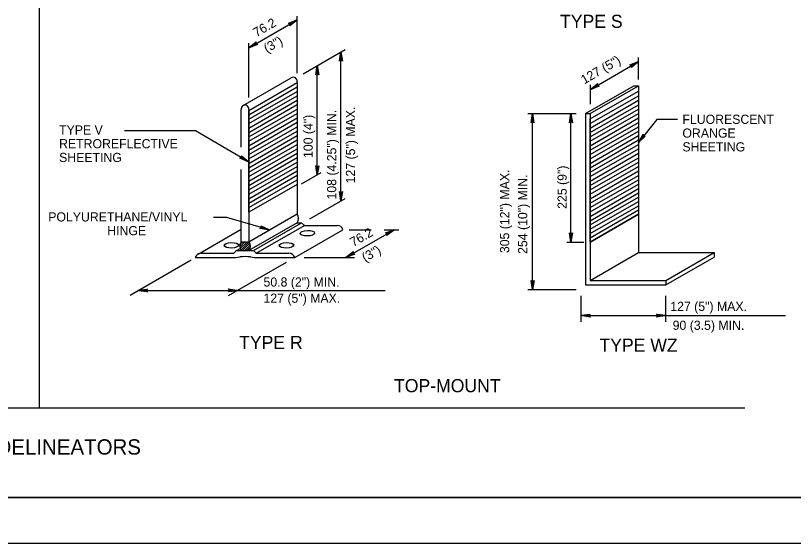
# Model space of a CAD drawing. Extents: x 640253 to 641999, y 298458 to 299646.
# Drawn here: x 640544.6 to 640798.8, y 298457.6 to 298630.1 of the extents above; entities that cross this region are included whole.
import ezdxf

# ---------------------------------------------------------------- set-up
doc = ezdxf.new("R2010")
doc.units = 0
for name, color, linetype in [('1', 7, 'Continuous'), ('2', 7, 'Continuous'), ('PLT-BNDY', 7, 'Continuous')]:
    doc.layers.add(name, color=color, linetype=linetype)

msp = doc.modelspace()

# ---------------------------------------------------------------- linework, layer by layer
at = {"layer": '1'}
for p, q in [((640552.4, 298501.97), (640552.4, 298787.67)), ((640318.26, 298501.97), (640782.88, 298501.97)), ((641079.31, 298472.63), (640293.31, 298472.63)), ((640293.31, 298472.63), (640879.31, 298472.63))]:
    msp.add_line(p, q, dxfattribs=at)
at = {"layer": '2'}
for p, q in [((640620.86, 298619.6), (640636.6, 298628.69)), ((640636.6, 298611.27), (640636.6, 298629.99)), ((640620.86, 298603.34), (640620.86, 298621.06)), ((640638.58, 298611.11), (640652.31, 298619.04)), ((640650.95, 298569.6), (640650.95, 298618.26)), ((640748.2, 298609.2), (640748.2, 298616.39)), ((640643.19, 298578.08), (640643.19, 298613.77)), ((640732.46, 298605.99), (640748.2, 298615.08)), ((640618.97, 298600.71), (640634.72, 298609.8)), ((640636.6, 298608.5), (640636.6, 298565.29)), ((640620.86, 298597.71), (640636.6, 298606.8)), ((640730.89, 298598.1), (640746.63, 298607.19)), ((640732.39, 298598.1), (640748.13, 298607.19)), ((640732.46, 298601.21), (640732.46, 298607.46)), ((640746.63, 298607.19), (640748.13, 298607.19)), ((640748.13, 298607.19), (640748.13, 298552.69)), ((640620.86, 298596.27), (640636.6, 298605.36)), ((640620.86, 298594.82), (640636.6, 298603.91)), ((640732.39, 298594.81), (640748.13, 298603.9)), ((640620.86, 298593.38), (640636.6, 298602.47)), ((640620.86, 298591.94), (640636.6, 298601.02)), ((640732.39, 298593.37), (640748.13, 298602.46)), ((640732.39, 298591.92), (640748.13, 298601.01)), ((640618.36, 298587.14), (640618.36, 298599.41)), ((640620.86, 298590.49), (640636.6, 298599.58)), ((640620.86, 298599.41), (640620.86, 298556.2)), ((640620.86, 298598.88), (640621.08, 298599.28)), ((640620.86, 298598.91), (640621.05, 298599.26)), ((640620.86, 298589.05), (640636.6, 298598.14)), ((640712.01, 298598.1), (640727.76, 298598.1)), ((640713.55, 298540.6), (640713.55, 298598.1)), ((640726.09, 298556.11), (640726.09, 298598.1)), ((640730.89, 298598.1), (640732.39, 298598.1)), ((640730.89, 298598.1), (640730.89, 298542.1)), ((640732.39, 298590.48), (640748.13, 298599.57)), ((640732.39, 298589.04), (640748.13, 298598.13)), ((640732.39, 298598.1), (640732.39, 298543.6)), ((640620.86, 298587.61), (640636.6, 298596.69)), ((640732.39, 298587.59), (640748.13, 298596.68)), ((640732.39, 298596.1), (640732.61, 298596.5)), ((640732.39, 298596.14), (640732.58, 298596.48)), ((640754.14, 298596.12), (640748.13, 298588.7)), ((640760.91, 298596.12), (640754.14, 298596.12)), ((640620.86, 298586.16), (640636.6, 298595.25)), ((640620.86, 298584.72), (640636.6, 298593.81)), ((640732.39, 298586.15), (640748.13, 298595.24)), ((640732.39, 298584.71), (640748.13, 298593.8)), ((640603.45, 298592.49), (640580.21, 298592.49)), ((640620.73, 298582.38), (640603.45, 298592.49)), ((640620.86, 298583.28), (640636.6, 298592.36)), ((640620.86, 298581.83), (640636.6, 298590.92)), ((640732.39, 298583.26), (640748.13, 298592.35)), ((640732.39, 298581.82), (640748.13, 298590.91)), ((640620.86, 298580.39), (640636.6, 298589.48)), ((640620.86, 298578.94), (640636.6, 298588.03)), ((640732.39, 298580.38), (640748.13, 298589.47)), ((640732.39, 298578.93), (640748.13, 298588.02)), ((640620.86, 298577.5), (640636.6, 298586.59)), ((640732.39, 298577.49), (640748.13, 298586.58)), ((640620.86, 298576.06), (640636.6, 298585.15)), ((640620.86, 298574.62), (640636.6, 298583.7)), ((640732.39, 298576.05), (640748.13, 298585.14)), ((640732.39, 298574.6), (640748.13, 298583.69)), ((640620.86, 298573.17), (640636.6, 298582.26)), ((640620.86, 298571.73), (640636.6, 298580.82)), ((640732.39, 298573.16), (640748.13, 298582.25)), ((640732.39, 298571.72), (640748.13, 298580.81)), ((640618.36, 298556.2), (640618.36, 298579.81)), ((640620.86, 298570.28), (640636.6, 298579.37)), ((640620.86, 298568.84), (640636.6, 298577.93)), ((640638.07, 298575.12), (640644.5, 298578.83)), ((640732.39, 298570.27), (640748.13, 298579.36)), ((640732.39, 298568.83), (640748.13, 298577.92)), ((640620.86, 298567.4), (640636.6, 298576.49)), ((640732.39, 298567.39), (640748.13, 298576.48)), ((640732.39, 298565.94), (640748.13, 298575.03)), ((640732.39, 298564.5), (640748.13, 298573.59)), ((640640.76, 298563.72), (640652.31, 298570.39)), ((640732.39, 298563.1), (640748.13, 298572.19)), ((640732.39, 298561.71), (640748.13, 298570.79)), ((640732.39, 298560.31), (640748.13, 298569.4)), ((640732.39, 298558.91), (640748.13, 298568)), ((640620.86, 298556.2), (640636.6, 298565.29)), ((640732.39, 298557.51), (640748.13, 298566.6)), ((640732.39, 298556.11), (640748.13, 298565.2)), ((640613.67, 298564.19), (640609.34, 298564.19)), ((640627.46, 298560.15), (640613.67, 298564.19)), ((640604.27, 298552.17), (640618.36, 298560.31)), ((640636.6, 298562.41), (640620.86, 298553.31)), ((640622.36, 298553.31), (640638.1, 298562.41)), ((640623.23, 298552.44), (640638.98, 298561.53)), ((640635.85, 298551.06), (640651.6, 298560.16)), ((640636.6, 298562.41), (640638.1, 298562.41)), ((640638.1, 298562.41), (640638.98, 298561.53)), ((640638.98, 298561.53), (640649.7, 298561.53)), ((640652.59, 298551.06), (640668.35, 298560.16)), ((640653.68, 298560.16), (640660.77, 298560.16)), ((640665.09, 298560.16), (640669.88, 298560.16)), ((640617.88, 298554.53), (640619.55, 298556.2)), ((640617.95, 298555.31), (640618.84, 298556.2)), ((640618.01, 298553.96), (640620.26, 298556.2)), ((640618.24, 298553.48), (640620.9, 298556.14)), ((640618.36, 298556.2), (640620.86, 298556.2)), ((640618.78, 298553.31), (640621.17, 298555.7)), ((640619.49, 298553.31), (640621.32, 298555.15)), ((640724.73, 298556.11), (640730.31, 298556.11)), ((640605.26, 298552.44), (640615.98, 298552.44)), ((640616.86, 298553.31), (640615.98, 298552.44)), ((640616.86, 298553.31), (640617.98, 298553.96)), ((640616.86, 298553.31), (640622.36, 298553.31)), ((640620.2, 298553.31), (640621.33, 298554.45)), ((640620.86, 298553.31), (640620.86, 298553.32)), ((640622.36, 298553.31), (640623.23, 298552.44)), ((640623.23, 298552.44), (640633.95, 298552.44)), ((640732.39, 298543.6), (640748.13, 298552.69)), ((640748.13, 298552.69), (640772.85, 298552.69)), ((640757.1, 298543.6), (640772.85, 298552.69)), ((640772.85, 298552.69), (640772.85, 298551.2)), ((640582.11, 298538.79), (640601.98, 298550.27)), ((640603.36, 298551.06), (640615.26, 298551.06)), ((640623.96, 298551.06), (640635.85, 298551.06)), ((640638.93, 298551.06), (640655.32, 298551.06)), ((640757.1, 298542.1), (640772.85, 298551.2)), ((640614.25, 298538.6), (640633.17, 298549.52)), ((640730.89, 298542.1), (640757.1, 298542.1)), ((640732.39, 298543.6), (640757.1, 298543.6)), ((640757.1, 298543.6), (640757.1, 298542.1)), ((640584.7, 298540.29), (640665.44, 298540.29)), ((640712.01, 298540.6), (640727.76, 298540.6)), ((640729.39, 298530.05), (640729.39, 298538.56)), ((640757.1, 298530.05), (640757.1, 298538.56)), ((640729.39, 298532.09), (640796.22, 298532.09))]:
    msp.add_line(p, q, dxfattribs=at)
for points in [[(640633.95, 298627.57), (640634.14, 298627.45), (640636.6, 298628.69), (640633.95, 298627.57), (640633.76, 298627.61), (640636.6, 298628.69), (640634.29, 298627.2), (640634.3, 298626.97), (640636.6, 298628.69), (640634.24, 298626.78), (640634.3, 298626.97)], [(640623.51, 298620.71), (640623.31, 298620.84), (640620.86, 298619.6), (640623.51, 298620.71), (640623.7, 298620.68), (640620.86, 298619.6), (640623.17, 298621.09), (640623.15, 298621.31), (640620.86, 298619.6), (640623.22, 298621.51), (640623.15, 298621.31)], [(640650.6, 298615.4), (640650.8, 298615.51), (640650.95, 298618.26), (640650.6, 298615.4), (640650.47, 298615.26), (640650.95, 298618.26), (640651.09, 298615.51), (640651.29, 298615.41), (640650.95, 298618.26), (640651.43, 298615.26), (640651.29, 298615.41)], [(640642.83, 298610.92), (640643.04, 298611.03), (640643.19, 298613.77), (640642.83, 298610.92), (640642.71, 298610.77), (640643.19, 298613.77), (640643.33, 298611.03), (640643.53, 298610.93), (640643.19, 298613.77), (640643.67, 298610.77), (640643.53, 298610.93)], [(640745.55, 298613.97), (640745.75, 298613.84), (640748.2, 298615.08), (640745.55, 298613.97), (640745.36, 298614), (640748.2, 298615.08), (640745.89, 298613.59), (640745.91, 298613.37), (640748.2, 298615.08), (640745.84, 298613.17), (640745.91, 298613.37)], [(640735.11, 298607.11), (640734.91, 298607.24), (640732.46, 298605.99), (640735.11, 298607.11), (640735.3, 298607.08), (640732.46, 298605.99), (640734.77, 298607.48), (640734.75, 298607.71), (640732.46, 298605.99), (640734.82, 298607.91), (640734.75, 298607.71)], [(640713.19, 298595.25), (640713.4, 298595.36), (640713.55, 298598.1), (640713.19, 298595.25), (640713.06, 298595.1), (640713.55, 298598.1), (640713.68, 298595.36), (640713.89, 298595.26), (640713.55, 298598.1), (640714.02, 298595.1), (640713.89, 298595.26)], [(640725.73, 298595.25), (640725.94, 298595.36), (640726.09, 298598.1), (640725.73, 298595.25), (640725.61, 298595.1), (640726.09, 298598.1), (640726.22, 298595.36), (640726.43, 298595.26), (640726.09, 298598.1), (640726.57, 298595.1), (640726.43, 298595.26)], [(640750.2, 298590.69), (640749.97, 298590.74), (640748.13, 298588.7), (640750.2, 298590.69), (640750.39, 298590.73), (640748.13, 298588.7), (640749.75, 298590.92), (640749.65, 298591.13), (640748.13, 298588.7), (640749.64, 298591.33), (640749.65, 298591.13)], [(640618.46, 298584.15), (640618.44, 298583.92), (640620.73, 298582.38), (640618.46, 298584.15), (640618.4, 298584.34), (640620.73, 298582.38), (640618.3, 298583.67), (640618.11, 298583.55), (640620.73, 298582.38), (640617.9, 298583.51), (640618.11, 298583.55)], [(640643.55, 298580.93), (640643.35, 298580.83), (640643.19, 298578.08), (640643.55, 298580.93), (640643.68, 298581.08), (640643.19, 298578.08), (640643.06, 298580.83), (640642.85, 298580.93), (640643.19, 298578.08), (640642.72, 298581.08), (640642.85, 298580.93)], [(640651.31, 298572.46), (640651.11, 298572.35), (640650.95, 298569.6), (640651.31, 298572.46), (640651.44, 298572.6), (640650.95, 298569.6), (640650.82, 298572.35), (640650.61, 298572.45), (640650.95, 298569.6), (640650.48, 298572.6), (640650.61, 298572.45)], [(640624.82, 298561.29), (640624.87, 298561.07), (640627.46, 298560.15), (640624.82, 298561.29), (640624.72, 298561.45), (640627.46, 298560.15), (640624.79, 298560.79), (640624.63, 298560.62), (640627.46, 298560.15), (640624.45, 298560.53), (640624.63, 298560.62)], [(640665.7, 298559.04), (640665.89, 298558.92), (640668.35, 298560.16), (640665.7, 298559.04), (640665.51, 298559.08), (640668.35, 298560.16), (640666.04, 298558.67), (640666.05, 298558.44), (640668.35, 298560.16), (640665.99, 298558.24), (640666.05, 298558.44)], [(640726.45, 298558.97), (640726.24, 298558.86), (640726.09, 298556.11), (640726.45, 298558.97), (640726.57, 298559.11), (640726.09, 298556.11), (640725.95, 298558.86), (640725.75, 298558.96), (640726.09, 298556.11), (640725.61, 298559.11), (640725.75, 298558.96)], [(640655.24, 298552.18), (640655.05, 298552.31), (640652.59, 298551.06), (640655.24, 298552.18), (640655.43, 298552.14), (640652.59, 298551.06), (640654.9, 298552.55), (640654.89, 298552.78), (640652.59, 298551.06), (640654.95, 298552.98), (640654.89, 298552.78)], [(640713.91, 298543.46), (640713.7, 298543.35), (640713.55, 298540.6), (640713.91, 298543.46), (640714.03, 298543.6), (640713.55, 298540.6), (640713.41, 298543.35), (640713.21, 298543.45), (640713.55, 298540.6), (640713.07, 298543.6), (640713.21, 298543.45)], [(640587.56, 298539.93), (640587.45, 298540.14), (640584.7, 298540.29), (640587.56, 298539.93), (640587.7, 298539.81), (640584.7, 298540.29), (640587.45, 298540.43), (640587.55, 298540.63), (640584.7, 298540.29), (640587.7, 298540.77), (640587.55, 298540.63)], [(640614.34, 298540.65), (640614.44, 298540.45), (640617.19, 298540.29), (640614.34, 298540.65), (640614.19, 298540.78), (640617.19, 298540.29), (640614.45, 298540.16), (640614.35, 298539.95), (640617.19, 298540.29), (640614.19, 298539.82), (640614.35, 298539.95)], [(640732.24, 298531.74), (640732.14, 298531.94), (640729.39, 298532.09), (640732.24, 298531.74), (640732.39, 298531.61), (640729.39, 298532.09), (640732.13, 298532.23), (640732.23, 298532.43), (640729.39, 298532.09), (640732.39, 298532.57), (640732.23, 298532.43)], [(640754.25, 298532.45), (640754.36, 298532.25), (640757.1, 298532.09), (640754.25, 298532.45), (640754.1, 298532.58), (640757.1, 298532.09), (640754.36, 298531.96), (640754.26, 298531.76), (640757.1, 298532.09), (640754.1, 298531.62), (640754.26, 298531.76)]]:
    msp.add_lwpolyline(points, dxfattribs=at)
for points in [[(640620.86, 298565.88), (640620.86, 298599.14), (640636.6, 298608.23), (640636.6, 298574.97)], [(640732.39, 298556.11), (640732.39, 298596.37), (640748.13, 298605.46), (640748.13, 298565.2)]]:
    msp.add_lwpolyline(points, close=True, dxfattribs=at)
for centre, radius, start, end in [((640635.35, 298608.7), 1.26, 350.9133, 119.9792), ((640619.61, 298599.61), 1.26, 350.9133, 189.0867), ((640634.82, 298563.85), 2.29, 320.9923, 39.0623), ((640649.7, 298559.53), 2, 18.187, 90), ((640620.14, 298554.76), 2.29, 140.9377, 219.0623), ((640619.08, 298554.76), 2.29, 320.9923, 39.0623), ((640605.26, 298550.44), 2, 90, 161.79), ((640633.95, 298550.44), 2, 18.21, 90), ((640615.26, 298569.81), 18.75, 270, 278.0038), ((640619.61, 298538.87), 12.5, 81.9962, 98.0038), ((640623.96, 298569.81), 18.75, 261.9962, 270)]:
    msp.add_arc(centre, radius, start, end, dxfattribs=at)
for centre in [(640639.98, 298559.01), (640615.17, 298555.06), (640633.14, 298555.06)]:
    msp.add_ellipse(centre, major_axis=(2.36, 0.05), ratio=0.379302, dxfattribs=at)
at = {"layer": 'PLT-BNDY'}
msp.add_lwpolyline([(640253.31, 299051.63), (641094.31, 299051.63), (641094.31, 298457.63), (640253.31, 298457.63)], close=True, dxfattribs=at)

# ---------------------------------------------------------------- texts
at = {"layer": '2'}
for s, rotation, p in [('76.2', 30, (640623.33, 298623.01)), ('(3")', 30, (640626.77, 298617.86)), ('127 (5")', 30, (640730.43, 298607.6)), ('108 (4.25") MIN.', 90, (640649.41, 298570.03)), ('127 (5") MAX.', 90, (640655.57, 298575.3)), ('100 (4")', 90, (640641.72, 298583.59)), ('225 (9")', 90, (640724.72, 298566.97)), ('305 (12") MAX.', 90, (640705.92, 298552.51)), ('254 (10") MIN.', 90, (640711.82, 298552.25)), ('76.2', 30, (640654.97, 298554.49)), ('(3")', 30, (640658.85, 298549.49))]:
    msp.add_text(s, height=3, rotation=rotation, dxfattribs=at).set_placement(p)
for s, height, p in [('TYPE S', 4.3, (640722.54, 298626.11)), ('FLUORESCENT', 3, (640762.52, 298594.73)), ('TYPE V', 3, (640558.85, 298591.26)), ('ORANGE', 3, (640762.52, 298590.23)), ('RETROREFLECTIVE', 3, (640558.85, 298586.76)), ('SHEETING', 3, (640762.52, 298585.73)), ('SHEETING', 3, (640558.85, 298582.26)), ('POLYURETHANE/VINYL', 3, (640555.3, 298562.84)), ('HINGE', 3, (640574.58, 298558.34)), ('50.8 (2") MIN.', 3, (640625.64, 298541.56)), ('127 (5") MAX.', 3, (640625.64, 298536.27)), ('127 (5") MAX.', 3, (640758.56, 298533.59)), ('90 (3.5) MIN.', 3, (640759.33, 298527.43)), ('TYPE R', 4.3, (640617.68, 298521.17)), ('TYPE WZ', 4.3, (640735.42, 298520.28)), ('TOP-MOUNT', 4.3, (640668.29, 298507.04)), ('BARRIER DELINEATORS', 5, (640506.83, 298486.66))]:
    msp.add_text(s, height=height, dxfattribs=at).set_placement(p)

doc.saveas('drawing.dxf')
